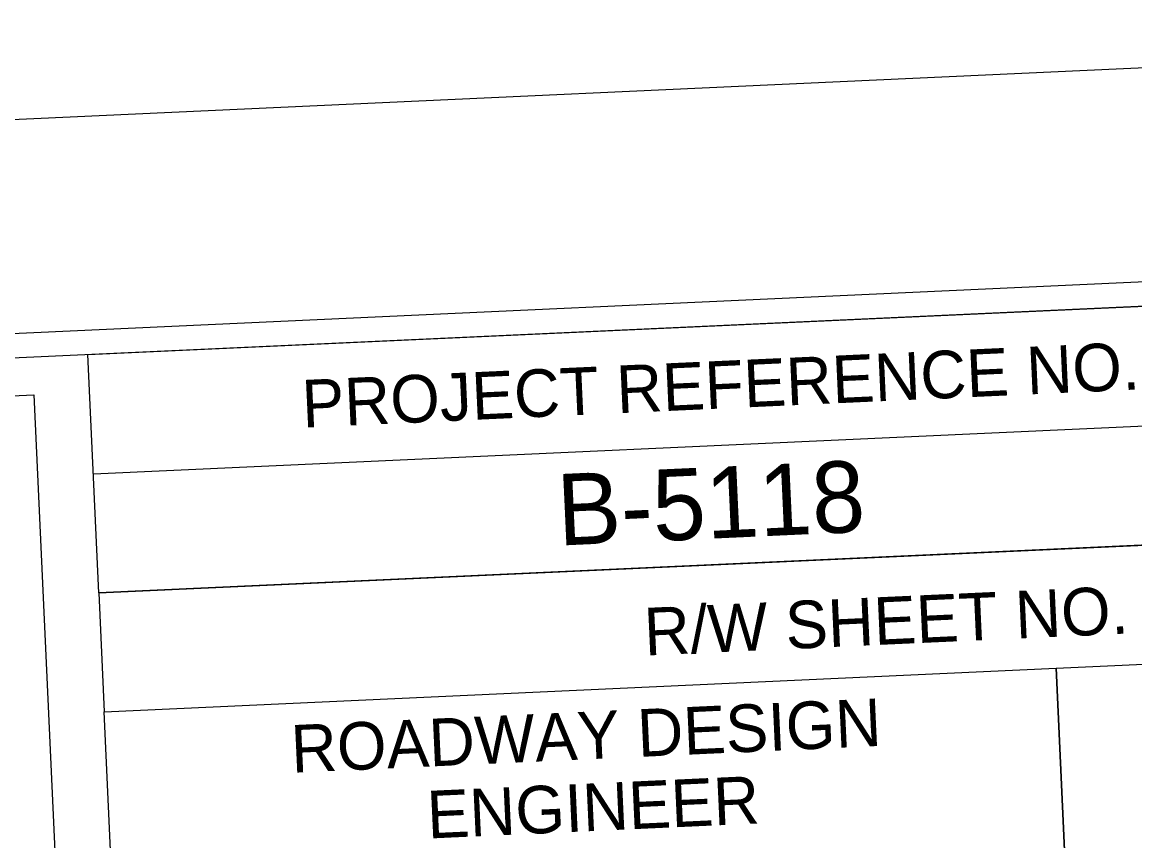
# Model space of a CAD drawing. Extents: x 1191067 to 1191874, y 892813 to 893283.
# Drawn here: x 1191700.79 to 1191747.52, y 893249.09 to 893283.47 of the extents above; entities that cross this region are included whole.
import ezdxf

# ---------------------------------------------------------------- set-up
doc = ezdxf.new("R2010")
doc.units = 0
for name, color, linetype in [('Sheet Border Standard 30in CELL', 7, 'Continuous'), ('Sheet Clip Boundary CELL', 7, 'Continuous'), ('Sheet Cutting Line CELL', 7, 'Continuous'), ('Sheet Data Field CELL', 7, 'Continuous'), ('Sheet Plot Border Inside CELL', 7, 'Continuous'), ('Sheet Plot Border Outside CELL', 7, 'Continuous')]:
    doc.layers.add(name, color=color, linetype=linetype)

msp = doc.modelspace()

# ---------------------------------------------------------------- linework, layer by layer
at = {"layer": 'Sheet Border Standard 30in CELL'}
for p, q in [((1191703.778, 893264.496), (1191783.714, 893268.153)), ((1191704.007, 893259.501), (1191783.943, 893263.158)), ((1191704.007, 893259.501), (1191783.943, 893263.158)), ((1191704.007, 893259.501), (1191704.235, 893254.507)), ((1191744.213, 893256.336), (1191746.269, 893211.403))]:
    msp.add_line(p, q, dxfattribs=at)
for points in [[(1191783.485, 893273.168), (1191184.112, 893245.747), (1191203.307, 892826.185), (1191802.68, 892853.607)], [(1191703.549, 893269.511), (1191783.485, 893273.168), (1191783.943, 893263.158), (1191704.007, 893259.501)], [(1191744.213, 893256.336), (1191784.171, 893258.164), (1191786.228, 893213.211), (1191746.27, 893211.383)], [(1191704.235, 893254.507), (1191744.213, 893256.336), (1191746.27, 893211.383), (1191706.292, 893209.554)]]:
    msp.add_lwpolyline(points, close=True, dxfattribs=at)
at = {"layer": 'Sheet Clip Boundary CELL'}
msp.add_lwpolyline([(1191202.887, 892905.773), (1191187.262, 893244.077), (1191701.27, 893267.817), (1191704.062, 893207.365), (1191782.861, 893211.004), (1191795.705, 892932.916), (1191477.617, 892917.949)], close=True, dxfattribs=at)
at = {"layer": 'Sheet Cutting Line CELL'}
msp.add_line((1191789.821, 893283.468), (1191116.925, 893252.683), dxfattribs=at)
at = {"layer": 'Sheet Plot Border Inside CELL'}
msp.add_lwpolyline([(1191788.433, 893274.415), (1191122.53, 893243.95), (1191141.818, 892822.351), (1191807.721, 892852.816)], close=True, dxfattribs=at)
at = {"layer": 'Sheet Plot Border Outside CELL'}
msp.add_lwpolyline([(1191789.821, 893283.468), (1191116.925, 893252.683), (1191137.034, 892813.143), (1191809.93, 892843.928)], close=True, dxfattribs=at)

# ---------------------------------------------------------------- texts
at = {"layer": 'Sheet Border Standard 30in CELL'}
for s, height, p in [('PROJECT REFERENCE NO.', 2.00004, (1191712.578, 893266.44)), ('R/W SHEET NO.', 2.00004, (1191726.951, 893256.867)), ('ROADWAY DESIGN', 2.00004, (1191712.12, 893251.944)), ('ENGINEER', 2, (1191717.833, 893249.182))]:
    msp.add_text(s, height=height, rotation=2.6195, dxfattribs=at).set_placement(p)
at = {"layer": 'Sheet Data Field CELL'}
msp.add_text('B-5118', height=3, rotation=2.6195, dxfattribs=at).set_placement((1191723.318, 893261.486))

doc.saveas('drawing.dxf')
